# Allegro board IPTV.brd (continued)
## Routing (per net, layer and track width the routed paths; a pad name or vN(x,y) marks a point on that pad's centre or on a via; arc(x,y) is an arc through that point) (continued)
USBHUB4_FLG: length 59.3
  TOP w0.152: U8.2 v1(99.49,119.67) ; v1(102.85,108.06) 109.2,108.06 111.02,106.23 111.02,84.82 110.01,83.81 101.02,83.81 100.31,83.1 U1.39
  BOTTOM w0.152: v1(102.85,108.06) 102.85,118.4 102.08,119.16 99.8,119.16 99.49,119.47 v1(99.49,119.67) 99.49,120.25 R615.2
USBHUB4_PWREN: length 58.3
  TOP w0.152: v1(103.35,108.62) 103.61,108.37 109.32,108.37 111.33,106.36 111.33,84.7 110.13,83.5 101.35,83.5 100.81,82.97 U1.38 ; U8.1 v1(100.14,119.67)
  BOTTOM w0.152: R614.2 100.14,120.23 v1(100.14,119.67) 100.34,119.47 102.21,119.47 103.35,118.32 v1(103.35,108.62)
USBHUB4_VBUS: length 1.8
  TOP w0.406: C439.1 102.21,113.96
  BOTTOM w0.508: R650.1 v1(100.75,116.5)
VREG3P3: length 5.3
  TOP w0.203: R321.2 C365.1 129.64,40.42 129.26,40.8 129.26,41.11 127.97,42.41 U18.35
XIN\G: length 12
  TOP w0.152: IC13.A7 v2(83.55,25.56)
  BOTTOM w0.152: XL1.1 84.68,16.83 R186.1 83.8,25.56 v2(83.55,25.56) 83.55,25.32 83.16,24.93 C272.1
XOUT\G: length 3
  TOP w0.152: v2(83.55,26.36) 83.15,26.77 IC13.B7
  BOTTOM w0.152: v2(83.55,26.36) 83.72,26.2 R186.2 R187.2
XTAL_IN: length 8.3
  TOP w0.152: U18.39 132.31,44.01 C242.1 135.25,45.27 Y4.3
XTAL_OUT: length 8.2
  TOP w0.152: R351.1 132.33,43.61 U18.38
XTAL_VDD2P5: length 2.3
  TOP w0.203: U18.40 128.67,44.41 128.88,44.61 C367.1
N305458: length 11.8
  TOP w0.381: IC13.L17 v2(75.55,33.56)
  BOTTOM w0.381: v2(75.55,33.56) 75.47,33.65
  BOTTOM w0.508: L7.1 76.37,23.6 C25.2 76.37,26.2 75.67,26.9 75.67,33.45 v2(75.55,33.56) ; 75.47,33.65 C41.2
N331283: length 13.8
  TOP w0.381: v2(74.75,32.78) 74.76,32.78 IC13.K17
  BOTTOM w0.508: C20.2 74.4,21.68 L1.1 74.32,23.55 74.91,24.14 C40.2 74.91,32.63 v2(74.75,32.78)
N371060: length 3
  TOP w0.127: IC13.AN34 61.15,51.97 v2(61.15,53.57)
  BOTTOM w0.152: R36.1 61.21,53.63 v2(61.15,53.57)
N550713: length 12.4
  TOP w0.381: v2(77.15,33.56) 76.76,33.17 IC13.K15 ; v2(76.35,33.56) 75.96,33.17 IC13.K16 ; IC13.K14 77.56,33.17 v2(77.95,33.56)
  BOTTOM w0.381: C157.1 v2(77.95,33.56) ; C21.1 v2(76.35,33.56) ; v2(77.15,33.56) 77.15,32.85
  BOTTOM w0.508: C157.1 77.15,32.85 ; 77.15,32.85 77.09,32.78 C7.1 C173.1 79.25,30.71 79.27,30.73 L2.1 80.07,30.67 C19.1 ; 77.15,32.85 C21.1
N600656: length 19.6
  TOP w0.381: IC13.P17 75.15,35.56 v2(74.75,35.16) ; IC13.P15 76.75,36.37 76.35,36.76 v2(76.35,36.76) 75.96,36.37 IC13.P16
  BOTTOM w0.508: L3.1 72.94,21.77 C24.1 72.98,24.46 C162.1 C158.1 73,30.85 73.18,31.03 73.18,34.1 73.53,34.45 C175.1 73.95,34.71 74.41,35.16 v2(74.75,35.16) 75.15,35.16 75.64,35.65 C159.1 75.64,36.01 76.35,36.73 v2(76.35,36.76)
N617373: length 3.4
  TOP w0.152: R65.1 90.39,32.97 89.09,32.97 88.09,33.97 IC13.L1
N617477: length 4.4
  TOP w0.152: R66.1 90.39,33.27 89.22,33.27 88.12,34.37 87.56,34.37 IC13.L2
N620918: length 4.4
  TOP w0.152: v2(82.54,35.57) IC13.N10
  BOTTOM w0.152: v2(82.54,35.57) 82.54,34.69 83.1,34.14 R71.1
N621324: length 7.6
  TOP w0.356: IC13.T11 79.85,37.86 79.85,37.27 IC13.R11 79.95,37.17 v2(80.35,36.76)
  TOP w0.381: IC13.P11 79.96,36.37 v2(80.35,36.76)
  BOTTOM w0.381: L5.1 79.87,36.32 79.91,36.32 v2(80.35,36.76)
  BOTTOM w0.406: C196.2 80.75,37.16 v2(80.35,36.76)
  BOTTOM w0.457: C63.1 81.07,35.65 C196.2 C67.2
N624580: length 11.1
  TOP w0.381: 81.15,36.76 80.76,36.37 IC13.P10 ; 81.15,36.76 81.36,36.76 v2(81.64,36.49) ; 81.15,36.76 IC13.R10
  BOTTOM w0.381: C186.2 82.95,36.49 v2(81.64,36.49) ; C186.2 83.47,35.54 83.8,35.22 85.95,35.22 L6.1 86.08,34.58 86.08,32.87 C48.1 ; C186.2 C180.2
N629124: length 6.3
  TOP w0.127: 89.41,46.44 86.66,46.44 86.59,46.38 85.94,46.38 IC13.AG4
  TOP w0.152: R70.1 90.83,46.44 89.41,46.44
N629220: length 3.6
  TOP w0.152: IC13.AG3 89.63,46.77 R70.2
N630094: length 6.6
  TOP w0.381: IC13.W10 v2(84.69,40.37)
  BOTTOM w0.381: R67.1 86.23,39.75 85.62,40.37 v2(84.69,40.37)
N631154: length 11.7
  TOP w0.381: v2(80.35,40.77) IC13.Y11 79.06,41.17 78.75,40.86 v2(78.75,38.36) ; IC13.AA11 79.96,41.97 v2(80.35,42.37)
  BOTTOM w0.381: L8.1 79.12,38 v2(78.75,38.36) ; 81.07,41.57 C201.2 v2(80.35,40.77) ; 81.07,41.57 83.95,41.57 C199.1 ; 81.07,41.57 C200.2 80.5,42.22 v2(80.35,42.37)
N635359: length 14.1
  TOP w0.381: v2(84.35,44.77) 84.35,44.45 84.1,44.2 82.42,44.2 82.04,43.81 82.04,42.42 81.59,41.97 IC13.AA10 IC13.Y10
  BOTTOM w0.381: L16.1 88.81,45.21 87.29,46.74 C197.1 87,46.67 87,45.83 86.18,45.02 84.61,45.02 v2(84.35,44.77) 84.27,44.68 C198.2
N672491: length 5
  TOP w0.127: IC13.C2 88.37,27.57 88.46,27.47 88.88,27.47
  TOP w0.152: 88.88,27.47 R54.1 89.41,27.88 89.51,27.98 R56.2
N675190: length 6.8
  TOP w0.127: IC13.D2 87.54,28.76 88.11,28.76 88.36,29 88.36,29.76
  TOP w0.152: 88.36,29.76 88.36,30.38 88.88,30.9 R52.1 89.41,31.3 89.51,31.41 R53.2
N675584: length 6.2
  TOP w0.127: 88.11,27.98 86.74,27.98 IC13.D3
  TOP w0.152: 88.11,27.98 88.77,27.98 R49.1 89.41,29.02 89.51,29.12 R50.2
N683964: length 5.7
  TOP w0.127: IC13.AJ4 85.94,48.76 86.58,48.76 87.01,49.19 89.11,49.19
  TOP w0.152: R64.1 89.11,49.19
N742106: length 4.4
  TOP w0.152: v2(66.75,28.79) 68.33,28.79 68.75,28.37 IC13.D25
  BOTTOM w0.152: v2(66.75,28.79) 66.27,28.79 65.91,28.44 R193.1
N743329: length 1.4
  TOP w0.152: v2(76.35,27.16) 76.35,27.17 IC13.C16
  BOTTOM w0.152: R194.1 76.47,27.28 v2(76.35,27.16)
N743719: length 2.1
  TOP w0.152: IC13.K29 65.19,33.53 v2(65.02,33.53)
  BOTTOM w0.152: R195.1 v2(65.02,33.53)
N744113: length 1.9
  TOP w0.152: IC13.L28 66.35,33.96 v2(65.95,33.56)
  BOTTOM w0.152: 65.02,32.64 65.03,32.64 v2(65.95,33.56)
N849049: length 5.5
  TOP w0.152: v1(55.48,39.83) 55.47,39.83 55.72,39.58 59.94,39.58 IC13.V36
  BOTTOM w0.152: v1(55.48,39.83) 55.47,39.83 55.47,40.64 R189.1
N854645: length 1.4
  TOP w0.152: v2(60.35,31.16) 59.95,30.77 IC13.G36
  BOTTOM w0.152: R190.1 60.27,31.25 v2(60.35,31.16)
N855285: length 4.4
  TOP w0.152: IC13.AB29 64.75,42.77 v2(64.29,42.31)
  BOTTOM w0.152: R17.1 62.38,40.86 63.08,41.55 63.82,41.55 64.29,42.02 v2(64.29,42.31)
N858511: length 3.7
  TOP w0.127: IC13.AB28 66.35,42.76 65.95,42.37 65.33,42.37
  TOP w0.152: 65.33,42.37 65.24,42.37 v2(64.52,41.64)
  BOTTOM w0.152: R283.1 63.78,40.91 v2(64.52,41.64)
N952727: length 10.4
  TOP w0.381: v2(81.15,43.17) 80.76,42.77 IC13.AB10
  BOTTOM w0.381: v2(81.15,43.17) 81.55,43.57 C56.2 81.87,43.23 82.25,42.85 84.67,42.85 85.48,42.04 C26.2 87.25,42.04 L34.2
N952924: length 6.2
  TOP w0.381: v2(80.35,43.97) 79.96,43.57 IC13.AC11
  BOTTOM w0.381: C57.2 81.7,44.59 81.7,44.54 81.38,44.22 80.61,44.22 v2(80.35,43.97) 80.32,44 78.78,44 L35.2 78.75,43.98 78.75,42.37 C28.2
N965277: length 2.2
  TOP w0.127: IC13.AT27 v2(66.75,54.37)
  BOTTOM w0.381: R226.2 66.75,54.75 v2(66.75,54.37)
N968462: length 10.2
  TOP w0.381: IC13.AR27 v2(66.75,53.57) ; IC13.AT28 v2(65.95,54.37)
  BOTTOM w0.381: L36.2 69.83,58.27 C59.1 C58.1 66.72,58.27 66.39,57.94 66.39,56.55 C30.1 65.28,55.04 v2(65.95,54.37) v2(66.75,53.57)
N1067717: length 7.7
  TOP w0.381: v2(68.35,47.17) 68.75,47.57 IC13.AH25
  BOTTOM w0.381: C31.2 66.11,43.19 67.24,43.19 L37.1 68.33,44.28 68.33,45.19 68.17,45.34 68.17,45.35 67.99,45.53 67.98,45.53 67.62,45.9 ; C61.2 67.62,45.9 ; 67.62,45.9 67.86,45.9 68.33,46.37 68.33,47.14 v2(68.35,47.17)
N1077748: length 18.4
  TOP w0.127: 57.15,52.1 57.28,51.98 59.56,51.98 IC13.AP36
  TOP w0.152: 57.15,52.1 55.85,53.41 45,53.41 44.55,53.86 44.55,55.18 44.3,55.43 R232.1
N1078134: length 49.1
  TOP w0.152: R232.2 43.92,57.29 37.62,63.59 37.62,65.58 34.77,68.42 34.77,70.52 29.49,75.81 19.84,75.81 15.11,80.53 15.11,84.71 15.49,85.09 C243.2 R240.1
N1094266: length 4
  TOP w0.127: 57.56,54.71 57.92,54.36 59.31,54.36 59.7,53.97 IC13.AT36
  TOP w0.152: R241.1 56.87,55.4 57.56,54.71
N1103649: length 5.3
  TOP w0.152: IC13.AT33 61.96,54.36 61.96,55.77 59.92,57.81 R237.1
N1103990: length 3.9
  TOP w0.152: IC13.AU32 62.67,55.24 62.67,56.84 62.21,57.31 R238.1
N1109849: length 6
  TOP w0.127: IC13.AT34 61.16,54.36 60.58,54.36 60.34,54.59 60.34,54.93 59.83,55.44 59.83,55.97 59.46,56.35
  TOP w0.152: R239.1 58.42,57.39 59.46,56.35
N1115694: length 5.4
  TOP w0.127: v2(65.15,54.37) IC13.AT30
  BOTTOM w0.152: v2(65.15,54.37) 64.39,54.37 63.98,54.77 63.98,56.29 63.35,56.92 R294.1
N1152398: length 3.4
  TOP w0.152: R111.1 R485.2 60.45,72.07 JP1.3
N1152811: length 3.4
  TOP w0.152: JP1.2 60.45,74.61 R101.1 R479.2
N1383679: length 9.2
  TOP w0.127: IC13.AT12 79.15,55.46
  TOP w0.152: R75.2 79.48,61.53 79.48,59.85 79.38,59.75 R77.2 78.51,59.29 78.51,56.44 79.15,55.8 79.15,55.46
N1387604: length 7.3
  TOP w0.127: 80.36,55.88 80.36,54.33 80,53.97 IC13.AT11
  TOP w0.152: 80.36,55.88 80.36,57.18 C207.2 80.82,57.19 80.95,57.31 80.95,59.78 C202.2
N1390073: length 11.8
  TOP w0.381: v2(77.95,48.77) 77.55,48.37 IC13.AJ14 IC13.AH14 ; IC13.AJ13 78.35,48.37 v2(78.75,48.77) ; IC13.AR10 80.75,53.16 v2(80.35,52.77)
  BOTTOM w0.381: C214.1 79.16,49.17 v2(78.75,48.77) ; C214.1 79.28,49.85 L21.2 ; C214.1 79.16,49.97 80.32,51.13 C217.1 80.32,52.73 v2(80.35,52.77) ; v2(78.75,48.77) 79.47,48.05 C221.1 ; v2(78.75,48.77) v2(77.95,48.77) C220.1
N1408395: length 6.9
  TOP w0.127: 77.63,56.1 77.96,55.77 77.96,54.36 IC13.AT13
  TOP w0.152: 77.63,56.1 77.32,56.41 R76.2 77.6,57.09 77.9,57.39 77.9,59.17 R74.2
N1409767: length 2.8
  TOP w0.152: v2(77.95,53.57) 77.55,53.17 IC13.AR14
  BOTTOM w0.152: C212.2 C205.2 78.11,53.72 v2(77.95,53.57)
N1414099: length 11.6
  TOP w0.305: IC13.AJ15 76.75,48.37 v2(76.35,48.77) ; v2(75.55,47.97) IC13.AH16 IC13.AH15
  BOTTOM w0.381: v2(76.35,48.77) C219.1 75.64,48.05 v2(75.55,47.97) 74.84,48.68 C216.1 74.84,50.04 C213.1 75.13,51.31 75.59,51.78 C215.1 75.59,53.39 L22.2
N1446091: length 2.8
  TOP w0.127: IC13.AU20 72.75,54.77 v2(73.15,54.37)
  BOTTOM w0.152: R80.1 R79.1 73.15,55.37 v2(73.15,54.37)
N1450972: length 18.9
  TOP w0.381: IC13.AH20 v2(73.15,47.17) ; v2(70.75,53.57) 71.15,53.97 IC13.AT22 ; v2(70.75,52.77) 71.15,53.17 IC13.AR22 ; v2(73.15,48.77) 72.75,48.37 IC13.AJ20
  BOTTOM w0.381: C227.1 68.76,49.33 69.15,48.93 L24.1 ; C227.1 68.99,50.2 72.11,50.2 72.44,49.88 C236.1 72.75,49.44 73.15,49.03 v2(73.15,48.77) v2(73.15,47.17) 73.07,47.08 C233.1 ; C227.1 68.76,50.84 69.11,51.19 C231.1 69.11,53.04 C237.1 69.5,53.12 69.85,52.77 v2(70.75,52.77) v2(70.75,53.57) 70.77,53.54 C235.1
N1496909: length 3.3
  TOP w0.381: IC13.AT8 82.35,53.97 v2(82.75,53.57)
  BOTTOM w0.381: C234.1 83.55,55.4 C232.1 82.8,53.52 v2(82.75,53.57)
N1501073: length 3.5
  TOP w0.381: v2(81.95,54.37) 81.55,53.97 IC13.AT9
  BOTTOM w0.381: C223.1 v2(81.95,54.37) 80.53,54.37 C225.1
N1511391: length 11.9
  TOP w0.381: IC13.AJ10 80.75,48.37 v2(81.15,47.97) 80.76,47.57 IC13.AH10 ; IC13.AR8 82.35,53.14 81.95,52.74 81.95,52.27 82.26,51.97 v2(82.75,51.97)
  BOTTOM w0.381: v2(82.75,51.97) 82.84,51.88 C230.1 L23.1 84.39,50.27 84.62,50.04 C226.1 84.48,49.02 82.03,49.02 81.87,48.86 C229.1 81.87,48.27 81.57,47.97 v2(81.15,47.97)
N1721272: length 37.1
  TOP w0.406: v1(30.46,73.19) 30.71,73.19 31.39,72.5 31.39,64.1 31.34,64.05
  TOP w0.508: v1(13.16,64.07) C222.2 R9.2
  BOTTOM w0.406: v1(30.46,73.19) 18.14,73.19 14.2,69.25 14.2,65.1 v1(13.16,64.07)
N1729801: length 1.5
  TOP w0.508: T7.3 9.75,61.76 R9.1
N1743891: length 3
  TOP w0.406: 8.8,56.49 v1(8.74,56.43)
  TOP w0.508: T7.1 8.8,56.49
  BOTTOM w0.508: R69.1 v1(8.74,56.43)
N1825143: length 6.2
  TOP w0.508: C307.1 153.62,4.45 R509.2 151.15,4.22 C308.2 149.99,1.85 D37.3
N1834854: length 3.5
  TOP w0.152: LED10.1 103.63,10.3 103.63,12.2 R414.2
N1835472: length 4.4
  TOP w0.152: R355.1 R368.1 R365.1 R414.1
N1837681: length 11.6
  TOP w0.152: R410.1 v1(102.21,11.34) ; R365.2 105.37,11.86 T3.3 107.29,9.94 106.51,9.17 LED10.2
  BOTTOM w0.152: v1(102.21,11.34) 102.86,11.34 LED10.2
N1839934: length 1.3
  TOP w0.152: R410.2 102.19,13.74 T6.1
N1841130: length 2.6
  TOP w0.152: T6.3 99.92,9.2 LED10.3
N1846118: length 3
  TOP w0.152: R276.1 R273.2 108.18,13.93 T3.1
N1848580: length 1.4
  TOP w0.152: R271.2 R273.1
N1851731: length 7.5
  TOP w0.152: LED11.2 120.53,9.65 T4.3
  BOTTOM w0.152: LED11.2 121.2,10.32 R472.2 R473.1
N1851759: length 1.7
  BOTTOM w0.152: R473.2 126.3,9.05 T5.1
N1851767: length 15.4
  TOP w0.152: LED11.3 116.04,8.08 127.86,8.08 128.36,8.58 v1(128.36,9.05)
  BOTTOM w0.152: T5.3 v1(128.36,9.05)
N1851843: length 3
  TOP w0.152: R458.1 R457.2 125.92,8.7 T4.1
N1851925: length 2.8
  TOP w0.152: R474.2 117.45,9.21 LED11.1
N2007180: length 4.9
  TOP w0.381: C36.1 93.38,106.51 R163.1 94.08,103.99 R28.2
N2007522: length 2
  TOP w0.381: R28.1 92.52,101.85 IC9.6
N2007610: length 1.5
  TOP w0.152: TP31.1 91.25,101.34 IC9.7
N2007630: length 1.5
  TOP w0.152: IC9.8 89.98,101.34 TP30.1
N2053816: length 12.4
  TOP w0.381: R87.2 131.32,95.38 v1(131.19,95.25) 130.85,94.91 IC5.1
  TOP w0.406: C171.2 117.7,96.94
  BOTTOM w0.406: C92.1 131.89,95.95 v1(131.19,95.25) 130.21,94.27 v1(124.18,94.27)
N2054287: length 8
  TOP w0.381: IC5.2 v1(130.2,95.41) 130.43,95.63 130.43,97.54 130.81,97.92 R87.1 R85.2
  BOTTOM w0.381: C92.2 129.48,96.14 v1(130.2,95.41)
N2062131: length 3
  TOP w0.381: R100.2 126.96,95.42 IC5.7
N2068150: length 3.2
  TOP w0.381: IC5.4 128.91,95.63 127.95,96.58 C163.2
N2072854: length 1.3
  BOTTOM w0.406: C165.2 128.12,87.41 v1(128.25,87.29)
N2075428: length 2.3
  TOP w0.381: IC5.12 v1(129.55,87.37)
  BOTTOM w0.381: v1(129.55,87.37) 129.64,87.46 C165.1
N2101818: length 2.3
  TOP w0.381: C167.1 129.55,96.38 IC5.3
N2116419: length 2.5
  TOP w0.406: R255.1 103.9,97.03 ; R254.2 99.69,96.52 ; R301.2 102.11,96.52
N2117665: length 1.5
  TOP w0.381: T2.3 99.72,94.2 R254.1
N2151179: length 5
  TOP w0.381: T2.1 98.77,90.21 99.16,89.83 101.7,89.83 102.11,90.23 R103.1
N2292443: length 3
  BOTTOM w0.152: IC2.10 100.45,52.64 R143.1
N2293018: length 2.9
  BOTTOM w0.152: IC2.6 98.45,52.82 R142.1
N2300583: length 3.1
  BOTTOM w0.152: R144.1 R145.2 100.95,30.08 IC2.38
N2472672: length 2.9
  TOP w0.508: IC12.8 151.32,65.09 151.76,64.64 152.88,64.64 C86.1
N2473836: length 5.6
  TOP w0.508: IC12.6 v1(148.78,68.2)
  BOTTOM w0.508: C89.1 C174.1 v1(148.78,68.2)
N2474741: length 2.1
  BOTTOM w0.508: C89.2 R104.1
N2480908: length 5.3
  TOP w0.508: R123.1 R82.2 150.62,67.69 150.05,67.12 IC12.7
N2490139: length 2.6
  TOP w0.508: IC12.1 v1(151.32,69.92)
  BOTTOM w0.508: v1(151.32,69.92) 151.32,69.92 C93.2
N2491369: length 1.3
  BOTTOM w0.508: C93.1 v1(148.91,72.58)
N2496811: length 5.3
  TOP w0.508: IC12.5 147.51,67.13 147.21,67.44 R109.1 R108.2
N2616362: length 16.2
  TOP w0.406: C109.2 44.93,73.06
  TOP w0.508: v1(48.49,92.49) R60.2 47.16,92.49 46.84,92.18 46.84,88.37 C87.1 47.03,86.33 46.33,85.64 46.33,80.43
  BOTTOM w0.381: IC26.1 47.94,91.94 v1(48.49,92.49)
N2616386: length 4.1
  TOP w0.406: C97.2 40.36,89.19 v1(40.23,89.32)
  BOTTOM w0.406: v1(40.23,89.32) 40.26,89.34 IC26.10 ; IC26.11 40.27,89.99 v1(40.23,89.95)
  vias: v1(38.33,89.32) v1(38.33,88.68) v1(38.96,89.32) v1(38.96,88.68) v1(39.6,89.32) v1(39.6,88.68)
N2616524: length 4.4
  BOTTOM w0.381: IC26.7 48.62,88.04 R61.2 R134.1 R135.1
N2616548: length 2.4
  TOP w0.381: v1(40.36,90.64) 40.44,90.72 C97.1
  BOTTOM w0.381: IC26.12 v1(40.36,90.64)
N2616572: length 2.9
  BOTTOM w0.381: IC26.3 48.8,90.64 C108.1
N2616768: length 5.2
  TOP w0.381: 47.6,90.97 R60.1
  TOP w0.508: R60.1 48.17,90.97 v1(48.49,91.29) 48.62,91.16 R55.2 49.57,91.1 R15.2
  BOTTOM w0.381: IC26.2 v1(48.49,91.29)
N2616804: length 2.7
  BOTTOM w0.381: IC26.4 49.53,89.99 C94.2
N2642107: length 1.8
  BOTTOM w0.508: C115.1 13.82,56.26 IC14.8
N2642151: length 7.3
  BOTTOM w0.508: IC14.6 11.28,55.41 10.98,55.71 8.18,55.71 7.47,56.43 C117.1 C116.1
N2642251: length 2.3
  BOTTOM w0.508: C116.2 6.2,60.3 R116.1
N2642341: length 2.3
  BOTTOM w0.508: IC14.1 15.69,49.48 C120.2
N2642373:
  vias: v1(13.31,52.62) v1(13.31,51.85) v1(13.31,51.09) v1(14.07,52.62) v1(14.07,51.85) v1(14.07,51.09) v1(14.83,52.62) v1(14.83,51.85) v1(14.83,51.09)
N2642473: length 2.8
  BOTTOM w0.508: R124.1 IC14.7
N2642609: length 5.1
  BOTTOM w0.508: R121.1 7.98,51.27 R120.2 9.71,53.59 10.01,53.89 IC14.5
N2653412: length 1.5
  BOTTOM w0.508: IC17.8 31.28,3.82 C348.1
N2653456: length 3.4
  BOTTOM w0.508: IC17.6 33.15,7.75 C118.1 C349.1
N2653460: length 7.7
  TOP w0.508: v1(35.66,6.48) 34.04,6.48 33.53,5.97 31.64,5.97 R51.1
  BOTTOM w0.508: C347.2 v1(35.66,6.48) R125.2
N2653540: length 1.4
  BOTTOM w0.508: C349.2 R583.1
N2653646: length 2.5
  TOP w0.508: C350.2 24.8,5.27 v1(24.74,5.21)
  BOTTOM w0.508: IC17.1 v1(24.74,5.21)
N2653678: length 2.5
  TOP w0.508: C350.1 24.8,7.68 v1(24.74,7.75)
  BOTTOM w0.508: IC17.3 v1(24.74,7.75)
  vias: v1(22.07,8.55) v1(22.07,7.91) v1(22.71,8.55) v1(22.71,7.91) v1(23.34,8.55) v1(23.34,7.91) v1(23.98,8.55) v1(23.98,7.91)
N2653726: length 10
  TOP w0.406: C380.1 20.04,25.06 ; C354.1 18.77,25.06
  TOP w0.508: C351.1 28.37,16.47 30.42,14.43 R563.1
N2653778: length 3.3
  BOTTOM w0.508: IC17.7 R125.1 R89.2
N2653914: length 5.8
  TOP w0.508: v1(32.49,9.02) 31.9,9.6 R563.2 R567.1
  BOTTOM w0.508: v1(32.49,9.02) IC17.5
N2764036: length 0.6
  TOP w0.406: C119.2 157.71,90.81 157.82,90.82
N2794854: length 3.3
  TOP w0.508: LED1.2 139.97,91.69 R122.1
N2987765: length 10
  BOTTOM w0.152: XL1.2 86.74,18.33 86.74,22.9 86.49,23.15 C274.1 R187.1
N4126175: length 3.4
  TOP w0.152: U1.47 96.31,84.38 R584.1 96.28,84.42 R585.2
N4126191: length 11.9
  TOP w0.254: U1.18 98.31,72.41 v1(98.31,72.4) ; U1.16 v1(97.31,72.43)
  TOP w0.508: R587.1 v1(96.75,68.83) 97.87,68.83 L49.2
  BOTTOM w0.381: v1(96.75,68.83) 96.75,71.98 97.19,72.43 v1(97.31,72.43) 97.04,72.7 C414.1 97.8,73.21 97.95,73.37 C413.1 98.31,72.4 v1(98.31,72.4)
N4126235: length 3.5
  TOP w0.203: U1.29 103.75,77.16 103.81,77.1 104.27,77.1 arc(104.57,77.04) 104.83,76.87 arc(105.08,76.7) 105.38,76.64 105.57,76.64 arc(105.84,76.75) R595.1
N4126359: length 3.5
  TOP w0.203: U1.28 103.75,76.66 103.78,76.69 104.27,76.69 arc(104.42,76.66) 104.54,76.58 arc(104.92,76.33) 105.38,76.24 105.6,76.24 arc(105.85,76.13) R594.1
N4126443: length 4.6
  TOP w0.152: U1.13 95.81,72.63 95.64,72.45 93.61,72.45 R586.2
N4126465: length 3.8
  TOP w0.203: U1.26 103.65,75.66 arc(103.69,75.65) 103.73,75.63 103.91,75.63 arc(104.08,75.59) 104.22,75.5 105.18,74.54 arc(105.37,74.41) 105.59,74.37 arc(105.85,74.48) R593.1
N4126501: length 3.9
  TOP w0.203: U1.25 103.7,75.16 103.76,75.22 103.91,75.22 arc(103.92,75.22) 103.93,75.21 104.89,74.25 arc(105.21,74.04) 105.59,73.96 arc(105.85,73.86) R592.1
N4126581: length 14.2
  TOP w0.508: R585.1 95.35,86.52 C405.1 95.13,86.52 C404.1 89,86.52 84.94,90.59 L47.2
N4126617: length 2.9
  TOP w0.152: R590.1 92.11,74.38 93.39,75.66 U1.11
N4126645: length 2.9
  TOP w0.254: R587.2 95.64,71.45 96.81,72.62 U1.15
N4126967: length 12.1
  TOP w0.254: U1.17 v1(97.81,75.11) ; U1.19 v1(98.81,75.11)
  TOP w0.381: L48.2 v1(102.37,72.58)
  BOTTOM w0.381: C414.2 97.41,75.11 v1(97.81,75.11) v1(98.81,75.11) 98.31,74.61 98.31,74.34 C413.2 98.72,74.33 98.94,74.1 98.94,73.64 99.24,73.34 101.61,73.34 v1(102.37,72.58)
N4126991: length 4.2
  TOP w0.152: R588.2 93.99,71.84 94.3,72.15 95.76,72.15 96.31,72.7 U1.14
N4127321: length 3.8
  TOP w0.203: U1.34 103.62,79.66 103.65,79.7 103.95,79.7 arc(104.22,79.75) 104.46,79.91 105.3,80.75 arc(105.38,80.8) 105.48,80.82 105.59,80.82 arc(105.85,80.71) R598.1
N4127377: length 3.8
  TOP w0.203: R599.1 105.96,81.57 arc(105.85,81.32) 105.59,81.23 arc(105.53,81.23) 105.48,81.23 arc(105.22,81.18) 105.01,81.03 104.17,80.19 arc(104.07,80.13) 103.95,80.1 103.68,80.1 103.62,80.16 U1.35
N4127493: length 3.5
  TOP w0.203: U1.32 103.59,78.66 103.64,78.61 104.26,78.61 arc(104.32,78.62) 104.37,78.66 arc(104.69,78.87) 105.06,78.94 105.59,78.94 arc(105.85,79.05) R597.1
N4127601: length 3.5
  TOP w0.203: U1.31 103.6,78.16 103.64,78.21 104.26,78.21 arc(104.48,78.25) 104.66,78.37 arc(104.84,78.49) 105.06,78.54 105.59,78.54 arc(105.85,78.43) R596.1
N4207901: length 3.4
  TOP w0.152: R600.1 91.83,78.67 93.35,77.16 U1.8
N4556901: length 2.8
  TOP w0.152: U5.5 127.93,103.42 127.51,103 R607.1
N4601170: length 2.2
  TOP w0.356: U6.5 154.78,45.25 R610.1
N4602996: length 2
  BOTTOM w0.152: U7.5 145.9,33.19 R613.1
N4604860: length 2.5
  TOP w0.152: R616.1 98.02,117.89 98.19,117.73 U8.5
N4652480: length 7.3
  TOP w0.152: R617.2 C0603.1 45.24,48.64 40.73,48.64 40.49,48.4 40.49,47.77 U9.T2
N4662264: length 5.4
  TOP w0.102: U9.L8 34.9,42.98 v1(33.42,42.98)
  BOTTOM w0.152: v1(33.42,42.98) 33.42,42.73 31.62,40.93 R618.2
N4946648: length 4.4
  TOP w0.102: U10.L8 46.1,9 46.1,7.43 46.04,7.37
  TOP w0.152: 46.04,7.37 46.04,7.24 v1(45.31,6.51)
  BOTTOM w0.152: v1(45.31,6.51) 45.06,6.26 R635.2
N4946958: length 7.9
  TOP w0.152: U10.T2 42,14.73 v1(42,18.33)
  BOTTOM w0.152: v1(42,18.33) 40.86,19.47 C473.1 39,19.47 R638.2
N5731377: length 2.4
  TOP w0.152: U11.5 v1(93.73,57.21)
  BOTTOM w0.152: v1(93.73,57.21) 93.42,56.91 R157.1
N5731391: length 2.3
  TOP w0.152: U11.2 v1(91.19,50.08)
  BOTTOM w0.152: R112.2 91.16,50.05 v1(91.19,50.08)
N5767868: length 5.1
  TOP w0.152: IC13.AT32 62.26,54.86 62.26,56.24 61.06,57.44 R160.1
N5876384: length 7.7
  TOP w0.127: IC13.AR30 64.36,53.56 64.36,55.71 64.01,56.07 64.01,56.77
  TOP w0.152: 64.01,56.77 64.01,59.85 R292.1
N5917875: length 2.8
  TOP w0.152: IC13.AV32 63.12,55.6 63.12,56.93 63.35,57.16 R296.1
N6200242: length 10.6
  TOP w0.305: R315.1 R316.1 R298.1 ; IC8.32 26.45,84.55 27.37,85.47 29.34,85.47 30.1,86.23 C239.1 R298.1 ; R298.1 31.73,86.13 R367.1
N6200318: length 5.7
  TOP w0.152: C113.2 19.3,83.06 19.43,83.19 R113.1 19.79,84.05 IC8.10
N6200334: length 1.4
  TOP w0.152: R114.2 32.41,83.27 LED5.2
N6200500: length 1.9
  TOP w0.152: R118.1 27.31,82.55 IC8.28
N6200912: length 3.3
  TOP w0.152: IC8.26 26.52,81.55 27.08,81 27.08,79.79 27.33,79.54 R299.2
N6200944: length 2.3
  TOP w0.152: R300.2 26.54,82.05 IC8.27
N6201102: length 40.2
  TOP w0.152: IC8.18 22.37,78.21 23.76,76.82 29.77,76.82 35.69,70.9 35.69,68.8 38.53,65.95 38.53,63.97 43.34,59.17 46.76,59.17 47.75,58.18 R302.2
N6210871: length 6.2
  TOP w0.508: R307.1 9.37,114.78 XS11.A8 9.34,116.09 XS11.A7
N6210911: length 2.5
  BOTTOM w0.152: C152.2 R303.2 R309.2
N6210999: length 15.8
  BOTTOM w0.152: TR2.16 16.84,106.88 16.84,111.51 15.54,112.81 15.54,115.28 16.77,116.52 17.39,116.52 XS11.A1
N6211019: length 16.1
  BOTTOM w0.152: TR2.14 17.14,106.93 17.14,111.63 15.84,112.94 15.84,115.16 16.9,116.21 17.47,116.21 17.73,115.95 17.73,115.58 XS11.A2
N6211031: length 6.2
  TOP w0.508: R306.1 14.42,111.77 XS11.A4 14.42,116.09 XS11.A5
N6211051: length 28.2
  BOTTOM w0.152: XS11.A3 15.69,116.27 15.49,116.08 14.86,116.08 14.57,116.36 14.57,118.15 14.99,118.57 18.92,118.57 29.57,107.93 29.57,106.91 TR2.11
N6211151: length 2.3
  TOP w0.508: R305.1 TR2.15
N6211171: length 2.3
  TOP w0.508: R304.1 TR2.10
N6211183: length 29.7
  BOTTOM w0.152: XS11.A6 12.58,114.82 14.27,116.5 14.27,118.28 14.86,118.87 19.05,118.87 29.87,108.05 29.87,106.91 TR2.9
N6211413: length 2.5
  BOTTOM w0.152: C151.2 R308.1 R310.1
N6211447: length 29
  TOP w0.508: C161.2 30.16,109.28 R304.2 R305.2 14.49,109.28 R306.2 14.42,109.28 9.41,109.28 R307.2
N6323561: length 42.5
  TOP w0.152: R154.2 45.21,57.88 44.53,58.56 43.08,58.56 37.92,63.72 37.92,65.7 35.08,68.55 35.08,70.65 29.62,76.11 20.57,76.11 20.17,76.52 20.17,81 20.72,81.55 IC8.15
N6351542: length 1.9
  TOP w0.152: IC8.13 20.65,82.55 20.4,82.3 R314.2
N6375056: length 3.9
  TOP w0.152: R126.1 24.47,88.25 24.47,87.41 23.77,86.72 23.77,85.87 23.87,85.77 IC8.4
N6376252: length 3.9
  TOP w0.152: R127.1 24.17,88.25 24.17,87.54 23.47,86.84 23.47,85.87 23.37,85.77 IC8.5
N6391887: length 4
  TOP w0.152: IC8.6 22.87,85.77 22.77,85.87 22.77,86.95 22.12,87.6 22.12,88.19 R128.1
N6393086: length 4
  TOP w0.152: R129.1 21.82,88.19 21.82,87.48 22.47,86.83 22.47,85.87 22.37,85.77 IC8.7
N6403944: length 1.8
  TOP w0.152: IC8.30 27.58,83.55 R130.1
N6828557: length 2
  TOP w0.152: R131.1 27.22,84.05 IC8.31
N6828959: length 1.3
  TOP w0.152: R131.2 TP33.1
N7088770: length 3.9
  BOTTOM w0.406: v1(53.7,73.06) C27.1 v1(52.62,74.14) ; v1(51.96,74.17) 51.96,74.34 52.3,74.68 C29.1 ; R19.2 v1(54.33,74.33)
N7088794: length 5
  TOP w0.508: U13.1 v1(55.87,78.52)
  BOTTOM w0.508: R19.1 R12.2 C46.2 55.86,78.51 v1(55.87,78.52)
N16840469: length 11.3
  TOP w0.127: IC13.R3 86.68,37.17 86.78,37.07 88.78,37.07 89,37.29 89.41,37.29
  TOP w0.152: R323.1 94.45,37.29 89.41,37.29
N16871257: length 12
  TOP w0.127: 89.41,37.59 88.89,37.59 88.62,37.32 86.88,37.32 86.65,37.56 86.15,37.56 85.74,37.97 IC13.T4
  TOP w0.152: 89.41,37.59 94.58,37.59 95.94,36.23 R325.1
N16883109: length 2.4
  TOP w0.152: IC13.B4 85.98,26.34 R327.1
N16907829: length 10.8
  TOP w0.127: IC13.T3 86.6,37.97 86.99,37.58 88.44,37.58 88.76,37.9 89.41,37.9
  TOP w0.152: 89.41,37.9 94.7,37.9 95.22,37.38 R328.1
N16928233: length 3.1
  TOP w0.127: IC13.N1 88.06,35.68 89.38,35.68 89.41,35.65
  TOP w0.152: 89.41,35.65 90.37,35.65 C358.2
N16929752: length 4
  TOP w0.127: IC13.N2 87.4,35.57 87.79,35.96 89.41,35.96
  TOP w0.152: 89.41,35.96 90.4,35.96 C359.2
N17005896: length 2.5
  BOTTOM w0.152: R107.1 107.75,93.26 T8.1
N17005931: length 6.9
  BOTTOM w0.508: C88.1 109.51,88.87 R331.1 107.93,88.68 Q10.1 R330.2 R322.2
N17006006: length 1.4
  BOTTOM w0.508: T8.3 R330.1
N17042686: length 2.7
  TOP w0.203: U18.44 128.31,46.01 129.33,47.03 C250.1
N17042698: length 6.1
  TOP w0.152: U18.46 128.21,46.81 129.68,48.27 132.06,48.27 R353.2
N17042736: length 3.5
  TOP w0.254: C372.1 117.98,22.52 C323.1 117.93,22.52 ANT1.1
N17042751: length 2.5
  TOP w0.254: R252.1 120.47,34.84 120.47,34.84 L44.2 120.47,33.54 C373.2
N17042774: length 4.9
  TOP w0.254: R334.1 126.47,34.71 ; 126.47,34.71 C240.1 126.47,34.71 ; 126.47,34.71 L39.2 L42.2 C332.2
N17042778: length 1.2
  TOP w0.254: L40.2 128.6,34.71 C240.2
N17042826: length 1.7
  TOP w0.152: U18.1 118.85,48.81 118.31,49.34 R335.2
N17042890: length 4.4
  TOP w0.254: ANT2.1 137.79,23.94 C376.1 137.77,27.11 C324.1
N17042953: length 3
  TOP w0.152: Y4.1 136.97,41.25 C224.1 R351.2
N17043028: length 4.2
  TOP w0.152: R340.1 128.5,39.92 128.25,40.17 128.25,41.61 127.8,42.06 126.94,42.06 126.84,41.95 U18.34
N17043046: length 1.5
  TOP w0.203: 120.44,41 U18.18
  TOP w0.254: C327.2 120.44,40.27 120.44,41
N17043052: length 8.2
  TOP w0.203: 122.04,40.27 U18.22
  TOP w0.254: 122.04,40.27 122.04,33.55 C334.2
N17043079: length 1.5
  TOP w0.152: C356.2 121.92,53.38 121.92,53.76 R337.1
N17043089: length 1.6
  TOP w0.152: R339.1 122.23,53.73 122.23,53.4 C357.2
N17043097: length 2.9
  TOP w0.152: C357.1 122.24,51.59 122.24,51.47 122.8,50.92 122.8,50.25 122.84,50.22 U18.62
N17043198: length 4.4
  TOP w0.152: U18.55 125.64,49.95 125.96,50.27 127.3,50.27 128.37,51.35 R319.1
N17043200: length 2.9
  BOTTOM w0.381: U23.4 112.01,42.43 111.74,42.71 L43.1
N17043207: length 7.6
  TOP w0.152: U18.47 128.18,47.21 129.55,48.58 131.45,48.58 132.72,49.85 R342.2 R338.1
N17043263: length 4.2
  BOTTOM w0.381: U23.6 113.31,43.68 R350.2 R348.2 C335.2
N17043371: length 1.7
  TOP w0.203: 126.04,40.8 U18.32
  TOP w0.254: C228.2 126.04,40.58 126.04,40.8
N17043377: length 13.6
  TOP w0.203: 124.44,40.36 U18.28
  TOP w0.254: C238.2 125.07,29.76 124.44,30.39 124.44,40.36
N17043650: length 1.5
  TOP w0.152: R29.1 LED8.1
N17043923: length 2.9
  TOP w0.152: U18.60 123.64,50.18 123.67,50.22 123.67,50.8 124.22,51.35 124.22,51.58 C194.1
N17044492: length 5.5
  TOP w0.152: U18.65 121.64,49.92 121.59,49.97 121.59,50.37 119.95,52.01 119.95,53.75 R343.1
N17044502: length 5.5
  TOP w0.152: R347.1 119.65,53.74 119.65,51.88 121.28,50.24 121.28,49.97 121.24,49.92 U18.66
N17044512: length 2.9
  TOP w0.152: U18.63 122.44,50.2 122.49,50.25 122.49,50.79 121.93,51.35 121.93,51.58 C356.1
N17044516: length 2.9
  TOP w0.152: C193.1 124.53,51.59 124.53,51.22 123.98,50.67 123.98,50.23 124.04,50.18 U18.59
N17044572: length 3.3
  TOP w0.152: U18.58 124.44,50.6 125.31,51.47 125.55,51.47 R341.1
N17044582: length 4
  TOP w0.152: R332.1 126.39,51.17 125.52,51.17 124.84,50.49 U18.57
N17044593: length 47.4
  TOP w0.152: U18.48 128.15,47.61 129.42,48.88 131.24,48.88 131.67,49.31 131.67,52.64 v1(131.06,53.25) ; v1(104.45,37.6) 104.34,37.5 R324.1
  BOTTOM w0.152: v1(131.06,53.25) 112.5,53.25 104.7,45.45 104.7,37.85 v1(104.45,37.6)
N17408441: length 4.3
  TOP w0.254: C387.1 149.1,14.77 C385.1 149.07,13.6 149.07,10.7 ANT3.1
N17408443: length 9.9
  TOP w0.254: ANT6.1 140.49,16.93 C386.1 149.1,15.79 C387.2
N17411597: length 3.6
  TOP w0.254: ANT4.1 10.01,87.77 C388.1 10.14,87.9 C390.1
N17411599: length 6.4
  TOP w0.254: ANT5.1 10.16,91.1 C389.1 10.16,89.95 C390.2
N17473278: length 2.3
  TOP w0.152: IC9.1 89.98,92.68 R115.2
N17474165: length 2.3
  TOP w0.152: IC9.2 91.25,92.68 R117.2
N17571775: length 16.3
  TOP w0.508: D5.2 v1(92.81,24.87)
  BOTTOM w0.508: L2.2 81.62,30.64 83.41,30.64 85.4,28.66 88.06,28.66 90.46,26.26 90.46,25.12 R178.2 90.72,24.87 v1(92.81,24.87)
N17602669: length 3.3
  TOP w0.152: R256.2 U20.2 R20.1
N17602677: length 6.8
  TOP w0.152: C391.1 R397.2 R357.2 R356.2 73.51,11.09 U20.3
N17621483: length 3.3
  TOP w0.254: R136.1 C60.2 65.58,102.37 U22.13
N17621510: length 4.8
  TOP w0.254: R7.2 63.53,104.3 63.27,104.56 63.27,106.56 63.55,106.84 R247.1 R258.2
N17621572: length 9.4
  TOP w0.254: R137.2 70.97,99.33 C181.1 70.99,99.88 71.22,100.11 76.3,100.11 76.56,100.37 R317.1 R359.1
N17621582: length 2.6
  TOP w0.254: U22.8 v1(68.3,105.62)
  BOTTOM w0.254: C34.2 68.35,105.57 v1(68.3,105.62)
N17621588: length 2.6
  TOP w0.254: U22.11 66.32,103.67 65.68,104.3 R7.1
N17621590: length 1.5
  TOP w0.254: U22.6 74.77,104.97 C35.2
N17621599: length 11.3
  TOP w0.254: R257.2 70.52,107.69 70.52,107.19 R360.1 70.52,106.5 70.52,103.29 70.79,103.02 U22.3 74.92,103.02 C62.2 R359.2
N17621615: length 3.1
  TOP w0.254: R317.2 C62.1 74.83,102.37 U22.2
N17621623: length 2.8
  TOP w0.254: R137.1 70.64,96.76 70.64,95.49 70.9,95.22 C268.2
N17621625: length 2.5
  TOP w0.254: U22.7 v1(72.24,105.62)
  BOTTOM w0.254: C34.1 72.19,105.57 v1(72.24,105.62)
N17621631: length 11.3
  TOP w0.254: R358.1 C60.1 65.5,103.02 U22.12 69.75,103.02 70.02,103.29 70.02,106.5 R133.1 70.02,107.19 70.02,107.69 R361.1
N17621647: length 9.6
  TOP w0.254: R90.1 69.8,98.08 C182.1 69.8,99.63 69.44,99.99 64.36,99.99 63.86,100.49 R136.2 63.98,101 R358.2
N17621657: length 2.8
  TOP w0.254: C393.1 69.94,95.22 70.13,95.41 70.13,96.79 R90.2
N17621659: length 6.7
  TOP w0.254: U22.5 75.28,104.32 R246.1 77.79,104.96 C53.1 R88.2
N17668644: length 5.4
  BOTTOM w0.508: Q9.1 19.41,34.96 R165.1 R10.2 19.41,29.9 C255.2
N17668703: length 2
  BOTTOM w0.508: T9.3 16.09,32.17 R10.1
N17668713: length 1.7
  BOTTOM w0.152: T9.1 13.96,29.64 R164.1
N17692840: length 6.7
  TOP w0.127: IC13.AU36 59.54,55.18 59.54,55.84 59.31,56.07
  TOP w0.152: R363.1 57.76,57.62 59.31,56.07
N17694055: length 6.5
  TOP w0.127: IC13.AU35 60.75,55.01 60.3,55.47 60.3,55.94 59.47,56.77
  TOP w0.152: R364.1 59.04,60.5 59.04,57.2 59.47,56.77
N17732186: length 3.1
  TOP w0.152: R171.2 81.76,55.16 81.37,54.77 IC13.AU10
N17732471: length 4.5
  TOP w0.152: R172.2 81.26,59.12 81.26,56.07 IC13.AV10
N17732758: length 2
  TOP w0.127: IC13.AV11 79.95,56.36 79.54,56.77
  TOP w0.152: 79.54,56.77 R173.2
N17739492: length 4.8
  TOP w0.152: IC13.AV14 76.73,56.39 76.73,59.19 R177.1
N17739788: length 2.9
  TOP w0.152: IC13.AU14 76.38,55.94 76.38,56.88 R176.1
N17782138:
  vias: v1(51.79,64.3) v1(51.79,63.41) v1(51.79,62.52) v1(52.55,64.3) v1(52.55,63.41) v1(52.55,62.52)
N17812204: length 3.1
  TOP w0.152: R475.2 133.83,6.53 LED12.1
N17850380: length 1.7
  TOP w0.152: R397.1 TP19.1

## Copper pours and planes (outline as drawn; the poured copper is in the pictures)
1V0\G on TOP: 46.71,67.73 46.71,62.27 46.46,62.01 44.17,62.01 43.92,62.27 43.92,67.73 44.3,68.11 46.33,68.11
1V0\G on BOTTOM: 44.3,65.44 44.04,65.7 44.04,67.73 44.43,68.11 49,68.11 49.12,67.98 49.12,65.57 49,65.44
1V0_CTRL\G on TOP: 47.47,73.44 49.76,73.44 50.01,73.19 50.01,70.14 49.76,69.89 47.6,69.89 47.35,70.14 47.35,73.32
1V0_CTRL\G on BOTTOM: 47.22,72.05 49.76,72.05 50.01,71.79 50.01,69.38 49.76,69.13 47.22,69.13 46.97,69.38 46.97,71.79
1V0_CTRL\G on L03_P2: 60.12,34.91 60.12,41.14 58.98,42.29 58.98,46.31 59.24,46.57 60.64,46.57 61.01,46.94 61.01,48.13 60.64,48.5 58.86,48.5 51.62,55.74 47.55,55.74 47.55,71.84 47.81,72.1 52.98,72.1 53.62,71.45 53.62,61.17 55.9,58.89 70,58.89 71.78,57.1 71.78,47.45 72.66,46.57 78.89,46.57 79.4,46.05 79.4,35.94 78.38,34.91
1V5_DDR3\G on TOP, BOTTOM: 30.58,26.96 35.66,26.96 35.92,26.71 35.92,24.8 35.66,24.55 30.58,24.55 30.33,24.8 30.33,26.71
1V5_DDR3\G on L03_P2: 41.97,6.08 40.31,7.74 40.31,13.2 34.72,18.79 34.72,30.22 29.77,35.17 29.77,50.37 34.73,55.33 51.45,55.33 58.69,48.09 60.47,48.09 60.6,47.96 60.6,47.11 60.47,46.98 59.07,46.98 58.57,46.48 58.57,42.12 59.72,40.97 59.72,34.03 58.57,32.89 58.57,26.88 59.07,26.38 64.96,26.38 65.46,26.88 65.46,28.66 65.85,29.04 67.46,29.04 67.84,28.66 67.84,22.94 71.65,19.14 76.85,19.14 77.24,18.75 77.24,18.28 76.98,18.02 75.52,18.02 73.43,15.93 73.43,8.88 72.79,8.24 57.42,8.24 56.79,7.61 56.79,6.22 56.66,6.08
1V5_DDR3_PHY\G on TOP: 64.52,27.43 64.14,27.81 64.14,28.57 63.88,28.83 63.37,28.83 61.47,30.73 61.47,31.37 61.72,31.62 61.72,34.04 61.59,34.16 59.82,34.16 59.69,34.29 59.69,34.8 59.82,34.92 61.47,34.92 61.59,35.05 61.59,38.99 61.34,39.24 60.58,39.24 60.45,39.37 60.45,39.66 60.64,39.85 60.66,39.85 61.34,40.54 61.34,41.02 61.21,41.15 61.09,41.15 60.83,40.89 60.58,40.89 60.45,41.02 60.45,41.27 61.34,42.16 61.34,46.74 60.96,46.74 60.45,46.23 60.2,46.23 59.82,46.61 59.82,46.99 60.71,46.99 61.34,47.62 61.34,49.78 59.69,51.44 59.69,51.56 59.82,51.69 60.07,51.69 60.58,51.18 64.39,51.18 64.64,50.93 64.64,42.16 65.02,41.78 66.04,41.78 66.17,41.66 66.17,41.02 67.94,41.02 68.2,40.77 68.2,36.58 69.41,35.37 72.07,35.37 75.44,32 75.44,29.72 75.06,29.34 65.28,29.34 65.02,29.08 65.02,27.56 64.9,27.43
1V5_DDR3_PHY\G on BOTTOM: 27.53,25.06 27.53,27.85 27.79,28.1 29.31,28.1 29.57,27.85 29.57,25.06 29.31,24.8 27.79,24.8
1V5_DDR3_PHY\G on L03_P2: 37.94,2.24 27.36,12.82 27.36,28.02 28,28.66 34.32,28.66 34.32,18.62 39.9,13.03 39.9,7.57 41.8,5.68 56.83,5.68 57.2,6.05 57.2,7.45 57.59,7.83 72.96,7.83 73.84,8.72 73.84,15.77 75.69,17.61 77.15,17.61 77.65,18.11 77.65,18.92 77.02,19.54 71.81,19.54 68.25,23.11 68.25,28.82 67.62,29.45 65.68,29.45 65.05,28.82 65.05,27.05 64.79,26.78 59.24,26.78 58.98,27.05 58.98,32.72 60.12,33.86 60.12,34.5 76.53,34.5 76.53,27.08 80.54,23.07 80.54,5.96 76.82,2.24
2V5\G on TOP: 135.89,71.79 136.27,72.17 136.27,78.11 135.76,78.61 125.09,78.61 124.21,77.72 124.21,72.26 124.68,71.79
3V3\G on TOP: 50.39,79.54 52.3,79.54 52.55,79.29 52.55,76.49 52.3,76.24 50.39,76.24 50.14,76.49 50.14,79.29
3V3\G on TOP: 14.33,74.33 14.83,74.84 22.26,74.84 23.72,73.38 26.71,73.38 27.28,72.81 27.28,65.7 26.9,65.32 15.09,65.32 14.33,66.08
3V3\G on TOP: 33.38,60.24 33.12,60.49 33.12,63.41 33.25,63.54 36.04,63.54 36.3,63.28 36.3,60.49 36.04,60.24
3V3\G on BOTTOM: 52.3,82.59 52.55,82.33 52.55,78.14 52.3,77.89 50.27,77.89 50.14,78.02 50.14,82.33 50.39,82.59
3V3\G on L03_P2: 34.85,55.74 34.85,57.14 33.59,58.41 27.49,58.41 23.04,62.86 23.04,71.45 23.43,71.84 26.31,71.84 26.7,71.45 26.7,66.25 29.61,63.33 36.64,63.33 37.9,64.6 37.9,73.49 44,79.59 52.72,79.59 52.86,79.46 52.86,72.5 47.64,72.5 47.14,72 47.14,55.74
3V3_MOS\G on TOP: 79.48,38.39 79.73,38.14 81.64,38.14 82.91,36.87 82.91,34.84 82.65,34.58 80.49,34.58 80.11,34.96 78.59,34.96 78.08,34.45 78.08,30.9 77.19,30.01 77.19,28.1 77.32,27.98 78.46,27.98 79.22,28.74 80.11,28.74 80.24,28.61 80.24,28.23 80.11,28.1 80.11,27.72 80.37,27.47 81.13,27.47 81.38,27.72 81.38,28.61 81.51,28.74 82.53,28.74 83.29,29.5 84.3,29.5 84.43,29.37 84.43,28.87 84.68,28.61 86.72,28.61 86.84,28.74 86.84,31.66 85.19,33.31 85.19,38.01 85.32,38.14 86.34,38.14 86.46,38.26 86.46,38.9 86.34,39.03 84.68,39.03 83.8,39.92 81.38,39.92 80.75,39.28 79.73,39.28 79.48,39.03
3V3_MOS\G on TOP: 35.92,64.05 35.79,63.92 32.49,63.92 31.85,64.55 31.85,66.2 32.11,66.46 35.54,66.46 35.92,66.08
3V3_MOS\G on TOP: 65,50.96 65,43.34 65.25,43.09 68.17,43.09 68.43,43.34 68.43,45.76 68.68,46.01 78.21,46.01 78.59,45.63 78.59,44.36 78.84,44.11 83.54,44.11 84.68,42.96 86.21,42.96 86.59,43.34 86.59,43.73 86.46,43.85 85.32,43.85 85.19,43.98 85.19,50.46 86.34,51.6 86.34,52.23 85.83,52.74 83.41,52.74 83.16,52.49 83.16,51.85 83.03,51.73 82.02,51.73 81.26,52.49 74.4,52.49 74.02,52.87 74.02,53.38 73.89,53.5 73.25,53.5 72.75,53 72.75,52.49 72.49,52.23 68.3,52.23 68.05,52.49 68.05,52.87 68.17,53 68.17,53.38 68.05,53.5 67.41,53.5 66.4,52.49 64.75,52.49 64.24,53 64.24,55.79 63.73,56.3 63.48,56.3 63.22,56.04 63.22,53.12 62.84,52.74 61.57,52.74 61.44,52.62 61.44,51.98 61.95,51.47 64.49,51.47
3V3_MOS\G on BOTTOM: 111.86,35.98 112.12,36.23 114.4,36.23 114.66,35.98 114.66,33.18 114.4,32.93 112.24,32.93 111.86,33.31
3V3_MOS\G on BOTTOM: 24.38,79.5 24.38,76.33 24,75.95 21.46,75.95 21.21,76.2 21.21,79.5 21.46,79.76 24.13,79.76
3V3_MOS\G on L03_P2: 80.95,12.43 80.95,23.24 76.94,27.25 76.94,34.5 78.55,34.5 79.81,35.77 79.81,46.22 79.05,46.98 72.83,46.98 72.19,47.62 72.19,57.27 70.16,59.3 56.07,59.3 54.03,61.34 54.03,71.62 53.26,72.38 53.26,82.63 54.25,83.62 116.76,83.62 116.93,83.46 121.18,79.21 138.58,79.21 144.96,72.82 152.23,72.82 152.86,73.45 152.86,75.01 149.28,78.59 149.28,87.5 145.98,90.79 134.13,90.79 132.35,89.01 125.41,89.01 123.16,91.26 84.04,91.26 80.96,94.35 40.15,94.35 34.95,89.15 34.95,83.69 28.97,77.71 16.94,77.71 16.21,78.44 16.21,89.87 15.71,90.37 14.56,90.37 14.05,90.89 14.05,100.04 39.68,100.04 40.69,101.05 40.69,106.29 34.73,112.25 29.4,112.25 23.71,117.94 38.29,117.94 39.81,119.47 49.55,119.47 53.23,115.78 91.63,115.78 97.6,121.75 102.63,121.75 103.66,120.73 103.66,108.54 104.41,107.78 142.51,107.78 151.02,99.27 161.69,99.27 166.52,94.44 166.52,30.3 146.9,30.3 144.73,32.47 144.73,58.89 141.69,61.93 107.1,61.93 104.7,59.52 104.7,12.43
5V0\G on TOP: 99.42,103.67 104.75,103.67 105.13,103.29 105.13,99.35 104.88,99.1 99.42,99.1 99.16,99.35 99.16,103.42
5V0\G on TOP: 32.61,57.57 32.61,54.65 32.36,54.39 28.68,54.39 28.42,54.65 28.42,56.81 27.92,57.31 24.49,57.31 23.98,57.82 23.98,58.97 24.36,59.35 28.42,59.35 29.95,57.82 32.36,57.82
5V0\G on BOTTOM: 107.29,87.54 111.61,87.54 111.99,87.16 111.99,83.86 111.74,83.6 107.16,83.6 106.91,83.86 106.91,87.16
5V0_MOS\G on TOP: 85.7,97.45 85.95,97.19 85.95,93.76 85.7,93.51 83.03,93.51 82.78,93.76 82.78,97.19 83.03,97.45
5V0_MOS\G on TOP: 129.79,104.52 130.05,104.27 130.05,103.12 130.3,102.87 135.13,102.87 135.38,103.12 135.38,105.79 135.13,106.05 130.3,106.05 130.18,105.92 130.18,105.28 129.92,105.03 128.14,105.03 128.02,104.9 128.02,104.65 128.14,104.52
5V0_MOS\G on TOP: 30.61,121.03 30.61,116.08 30.35,115.82 28.7,115.82 28.32,116.2 28.32,121.03 28.45,121.16 30.48,121.16
5V0_MOS\G on TOP: 149.58,30.52 149.33,30.77 149.33,35.22 149.71,35.6 154.79,35.6 155.3,36.11 155.3,40.42 155.04,40.68 153.65,40.68 153.26,41.06 153.26,44.49 153.39,44.61 153.65,44.61 153.77,44.49 153.77,42.84 153.9,42.71 159.11,42.71 159.36,42.46 159.36,33.95 158.09,32.68 152.12,32.68 151.61,32.17 151.61,30.77 151.36,30.52
5V0_MOS\G on BOTTOM: 148.57,33.95 148.57,31.15 148.82,30.9 150.22,30.9 150.47,31.15 150.47,34.33 149.96,34.84 146.63,34.84 146.58,34.78 146.58,34.3 146.63,34.25 148.26,34.25
5V0_MOS\G on BOTTOM: 98.91,113.7 99.16,113.96 99.16,118.66 98.91,118.91 96.62,118.91 96.24,118.53 96.24,113.96 96.5,113.7
5V0_VBUS0\G on TOP: 98.4,103.29 98.4,95.41 98.15,95.16 96.62,95.16 96.37,95.41 96.37,103.29 96.75,103.67 98.02,103.67
5V0_VBUS1\G on BOTTOM: 102.85,89.7 105.77,89.7 106.02,89.45 106.02,84.37 105.64,83.98 103.35,83.98 102.72,84.62 102.72,89.57
12V\G on TOP: 18.14,4.23 18.52,3.85 22.96,3.85 23.34,4.23 23.34,6.64 23.09,6.9 18.52,6.9 18.14,6.51
12V\G on TOP: 150.62,72.14 150.62,70.36 150.5,70.23 149.73,70.23 149.61,70.36 149.61,76.71 149.99,77.09 155.57,77.09 155.96,76.71 155.96,72.9 155.57,72.52 151,72.52
12V\G on TOP: 41.63,95.03 41.89,94.78 41.89,91.22 41.63,90.97 37.57,90.97 37.19,91.35 37.19,94.65 37.57,95.03
12V\G on TOP: 132.06,91.19 136.79,91.19 137.64,90.33 147.03,90.33 147.45,89.92 147.45,83.75 147.3,83.6 135.87,83.6 135.1,84.37 130.53,84.37 129.9,85 129.9,89.19 130.02,89.32 131.42,89.32 131.8,89.7 131.8,90.93
12V\G on BOTTOM: 27.03,6.77 27.03,5.88 26.9,5.75 24.61,5.75 24.36,5.5 24.36,4.1 24.11,3.85 19.28,3.85 19.03,4.1 19.03,6.64 19.28,6.9 26.9,6.9
12V\G on BOTTOM: 13.18,50.2 13.18,48.55 13.56,48.17 16.74,48.17 16.99,47.92 16.99,45.63 16.87,45.5 8.48,45.5 8.23,45.76 8.23,47.92 8.48,48.17 11.66,48.17 12.04,48.55 12.04,50.2 12.17,50.33 13.06,50.33
12V\G on BOTTOM: 42.39,94.53 42.39,91.1 42.27,90.97 37.57,90.97 37.19,91.35 37.19,94.65 37.57,95.03 41.89,95.03
12V\G on L03_P2: 19.11,4.05 17.2,5.96 17.2,42.92 14.92,45.2 10.98,45.2 10.59,45.59 10.59,55.07 11.74,56.21 11.74,64.72 16.94,69.93 16.94,77.3 29.14,77.3 35.36,83.52 35.36,88.98 40.32,93.94 80.79,93.94 83.88,90.86 122.99,90.86 125.24,88.61 132.52,88.61 134.3,90.38 145.81,90.38 148.87,87.33 148.87,78.43 152.45,74.85 152.45,73.62 152.06,73.23 145.13,73.23 138.74,79.62 121.34,79.62 117.21,83.75 116.92,84.02 54.08,84.02 52.86,82.8 52.86,80 43.83,80 37.49,73.65 37.49,64.76 36.47,63.74 29.78,63.74 27.1,66.42 27.1,71.62 26.48,72.25 23.26,72.25 22.63,71.62 22.63,62.69 27.32,58 33.42,58 34.44,56.98 34.44,55.62 29.36,50.54 29.36,35.01 34.32,30.05 34.32,29.07 27.83,29.07 26.95,28.19 26.95,12.65 35.55,4.05
+1V2 on BOTTOM: 112.62,44.61 108.56,44.61 108.31,44.87 108.31,48.42 108.81,48.93 112.62,48.93 112.88,48.68 112.88,44.87
+1V2 on L03_P2: 110.67,43.17 110.67,48.35 114.57,48.35 115.21,47.71 115.21,46.82 115.72,46.32 116.9,46.32 117.4,46.82 117.4,48.21 119.19,50 128.29,50 128.8,49.48 128.8,48.76 128.42,48.37 120.54,48.37 120.04,47.87 120.04,44.44 118.76,43.17
GND on TOP, BOTTOM, L02_P1: 5.42,1.02 1.02,5.42 1.02,100.04 39.68,100.04 40.69,101.05 40.69,106.29 34.73,112.25 29.4,112.25 20.76,120.89 1.02,120.89 1.02,122.88 5.42,127.28 94.48,127.28 94.48,124.24 98.52,124.24 98.52,127.28 150.48,127.28 150.48,105.98 163.58,105.98 167.98,101.58 167.98,5.42 163.58,1.02 144.42,1.02 139.42,6.02 84.08,6.02 79.08,1.02
GND on L03_P2: 5.42,1.02 1.02,5.42 1.02,100.04 13.64,100.04 13.64,90.72 14.39,89.97 15.54,89.97 15.8,89.7 15.8,78.27 16.57,77.51 16.54,77.48 16.54,70.1 11.33,64.89 11.33,56.38 10.19,55.24 10.19,45.42 10.81,44.79 14.75,44.79 16.79,42.75 16.79,5.8 18.94,3.64 35.75,3.64 35.85,3.75 37.77,1.83 76.98,1.83 80.95,5.8 80.95,12.03 105.11,12.03 105.11,59.35 107.27,61.52 141.52,61.52 144.32,58.72 144.32,32.3 146.73,29.9 166.93,29.9 166.93,94.61 161.86,99.68 151.19,99.68 142.68,108.19 104.58,108.19 104.06,108.71 104.06,120.9 102.8,122.16 97.43,122.16 91.46,116.19 53.4,116.19 49.72,119.87 39.64,119.87 38.12,118.35 23.3,118.35 20.76,120.89 1.02,120.89 1.02,122.88 5.42,127.28 94.48,127.28 94.48,124.24 98.52,124.24 98.52,127.28 150.48,127.28 150.48,105.98 163.58,105.98 167.98,101.58 167.98,5.42 163.58,1.02 144.42,1.02 139.42,6.02 84.08,6.02 79.08,1.02 ; 1 cut-out
VCC_3.3V on TOP: 137.39,57.82 137.64,57.57 137.64,56.3 137.48,56.13 132.33,56.13 132.08,56.39 132.08,57.53 132.37,57.82
VCC_3.3V on BOTTOM: 112.88,40.3 112.88,39.28 113.01,39.15 114.53,39.15 114.78,38.9 114.78,37.38 114.53,37.12 110.34,37.12 110.08,37.38 110.08,40.93 110.21,41.06 111.35,41.06 111.48,40.93 111.48,40.55 111.61,40.42 112.75,40.42
VCC_3.3V on L03_P2: 128.96,35.42 128.32,36.06 128.32,39.49 127.6,40.21 121.96,40.21 121.45,39.7 120.82,39.7 120.35,39.23 113.18,39.23 112.55,38.6 112.55,37.08 112.16,36.69 111.06,36.69 110.67,37.08 110.67,42.76 118.93,42.76 120.45,44.28 120.45,47.71 120.71,47.97 128.58,47.97 129.21,48.59 129.21,49.65 128.46,50.41 119.02,50.41 116.99,48.38 116.99,46.98 116.73,46.72 115.88,46.72 115.62,46.98 115.62,47.87 114.74,48.75 110.67,48.75 110.67,49.23 113.94,52.5 131.59,52.5 132.51,53.42 132.51,57.48 133.03,58 134.77,58 135.56,57.21 135.56,36.98 134,35.42
VCC_SCI\G on TOP: 21.46,55.54 20.83,54.9 20.83,34.04 21.55,33.31 24.49,33.31 24.99,33.82 24.99,54.77 24.23,55.54
VCC_SCI\G on BOTTOM: 25.53,41.91 21.34,41.91 21.08,42.16 21.08,44.7 21.34,44.96 25.53,44.96 25.78,44.7 25.78,42.16
USBHUB1_VBUS on TOP: 126.49,103.76 126.24,104.01 126.24,107.82 126.87,108.46 128.91,108.46 129.54,109.09 129.54,117.86 129.03,118.36 126.87,118.36 126.49,117.98 126.49,115.82 126.11,115.44 123.95,115.44 123.7,115.7 123.7,120.78 124.08,121.16 133.86,121.16 134.75,120.27 134.75,107.44 134.24,106.93 130.68,106.93 129.92,106.17 129.92,105.41 129.67,105.16 128.02,105.16 127.89,105.03 127.89,104.39 128.02,104.27 129.67,104.27 129.79,104.14 129.79,103.89 129.67,103.76
USBHUB2_VBUS on TOP: 153.01,44.74 153.01,43.22 152.76,42.96 149.2,42.96 148.57,43.6 148.57,48.55 148.95,48.93 154.03,48.93 154.09,48.87 155.49,48.87 155.8,48.55 155.8,47.03 155.55,46.77 154.53,46.77 154.41,46.65 154.41,43.09 154.28,42.96 154.15,42.96 154.03,43.09 154.03,44.74 153.9,44.87 153.14,44.87
USBHUB3_VBUS on TOP: 148.44,33.69 148.18,33.44 144.63,33.44 144.5,33.57 144.5,37.5 145.77,38.77 145.77,40.42 146.03,40.68 148.06,40.68 148.44,40.3
USBHUB3_VBUS on BOTTOM: 148.06,33.57 145.26,33.57 145.14,33.69 145.14,35.72 145.26,35.85 148.06,35.85 148.18,35.72 148.18,35.09 148.06,34.96 146.53,34.96 146.41,34.84 146.41,34.2 146.53,34.07 148.06,34.07 148.18,33.95 148.18,33.69
USBHUB4_VBUS on TOP: 96.88,114.59 97.38,115.1 98.27,115.1 98.53,115.35 98.53,117.64 98.65,117.77 98.91,117.77 99.04,117.64 99.04,115.86 99.16,115.73 99.8,115.73 99.92,115.86 99.92,117.77 99.99,117.83 99.99,118.46 102.59,121.07 108.56,121.07 109.58,120.05 109.58,115.73 109.2,115.35 107.04,115.35 106.78,115.61 106.78,117.77 106.27,118.27 104.24,118.27 103.23,117.26 103.23,110.15 102.72,109.64 97.38,109.64 96.88,110.15
N1721272 on TOP: 32.36,59.98 32.61,59.73 32.61,58.71 32.36,58.46 30.07,58.46 29.44,59.09 29.44,60.74 29.95,61.25 29.95,63.16 29.57,63.54 29.57,64.81 29.69,64.93 30.96,64.93 32.36,63.54
N2053816 on TOP: 117.32,98.08 124.31,98.08 124.69,97.7 124.69,91.22 124.05,90.59 117.7,90.59 116.94,91.35 116.94,97.7
N2072854 on TOP: 129.13,89.19 129.13,81.06 128.75,80.68 119.1,80.68 117.7,82.08 117.7,85.64 118.59,86.52 127.23,86.52 127.99,87.29 127.99,89.19 128.12,89.32 129.01,89.32
N2116419 on TOP: 99.29,98.46 104.24,98.46 104.5,98.21 104.5,95.54 104.33,95.38 99.29,95.38 98.91,95.76 98.91,98.08
N2491369 on TOP: 149.22,70.36 149.1,70.23 148.34,70.23 148.21,70.36 148.21,72.26 147.92,72.55 142.47,72.55 141.86,73.16 141.86,78.23 142.49,78.87 148.72,78.87 149.22,78.36
N2616362 on TOP: 46.01,73.76 46.01,69.44 45.06,68.49 40.11,68.49 39.09,69.51 39.09,79.54 40.23,80.68 49.63,80.68 49.89,80.43 49.89,75.09 49.38,74.59 46.84,74.59
N2616386 on TOP: 44.68,86.26 44.68,82.71 44.17,82.21 38.46,82.21 38.08,82.59 38.08,89.45 38.42,89.79 41.91,89.79 42.16,89.53 42.16,87.25 42.67,86.74 44.2,86.74
N2616386 on BOTTOM: 42.39,90.08 42.39,89.19 42.27,89.06 40.23,89.06 39.98,88.81 39.98,88.68 39.73,88.43 38.08,88.43 37.95,88.56 37.95,89.95 38.2,90.21 42.27,90.21
N2642373 on TOP: 13.31,62.39 22.33,62.39 22.84,61.89 22.84,57.7 22.39,57.25 20.95,57.25 17.65,53.95 17.65,50.93 17.44,50.71 13.31,50.71 12.93,51.09 12.93,62.01
N2642373 on BOTTOM: 11.79,50.33 11.79,48.68 11.66,48.55 10.9,48.55 10.77,48.68 10.77,52.74 11.15,53.12 16.99,53.12 17.25,52.87 17.25,51.09 16.87,50.71 12.17,50.71
N2653678 on TOP: 24.87,14.13 24.87,7.91 24.49,7.53 18.14,7.53 17.76,7.91 17.76,14.01 18.26,14.52 24.49,14.52
N2653678 on BOTTOM: 27.03,8.29 27.03,7.28 26.9,7.15 21.82,7.15 21.57,7.4 21.57,8.67 21.82,8.93 24.61,8.93 25.12,8.42 26.9,8.42
N2653726 on TOP: 14.71,26.33 29.06,26.33 29.31,26.07 29.31,18.07 28.93,17.69 15.09,17.69 13.95,18.83 13.95,25.56
N2753223 on TOP: 155.57,96.39 143.76,96.39 141.86,98.3 141.86,119.51 142.37,120.02 148.59,120.02 149.1,119.51 149.1,106.81 151.64,104.27 155.32,104.27 155.96,103.63 155.96,96.77
N2764036 on TOP: 150.62,88.77 150.62,82.17 151.57,81.22 164.91,81.22 165.35,81.66 165.35,91.06 164.85,91.57 156.46,91.57 156.21,91.31 156.21,89.92 155.7,89.41 151.26,89.41
N2782469 on TOP: 161.16,92.2 153.92,92.2 153.29,92.84 153.29,95.5 153.8,96.01 156.97,96.01 158.12,97.16 161.16,97.16 161.54,96.77 161.54,92.58
N2978313 on TOP: 161.52,47.15 161.27,46.9 156.82,46.9 156.57,47.15 156.57,50.96 156.95,51.35 161.14,51.35 161.52,50.96
N2982528 on TOP: 157.33,23.02 161.14,23.02 161.52,22.64 161.52,18.33 161.27,18.07 157.46,18.07 157.07,18.45 157.07,22.77
N7088770 on TOP: 57.63,66.46 57.63,75.09 57.25,75.48 55.22,75.48 54.97,75.73 54.97,77.76 54.71,78.02 53.19,78.02 52.93,77.76 52.93,75.73 52.68,75.48 51.66,75.48 51.16,74.97 51.16,66.46 51.79,65.82 57,65.82
N7088770 on BOTTOM: 50.01,65.7 56.87,65.7 57.63,66.46 57.63,73.32 57.25,73.7 51.79,73.7 51.66,73.57 51.66,69.89 49.63,67.86 49.63,66.08
N17782138 on TOP: 48.49,65.32 52.68,65.32 52.93,65.06 52.93,62.39 52.68,62.14 48.62,62.14 48.24,62.52 48.24,65.06
N17782138 on BOTTOM: 48.62,64.81 52.55,64.81 52.93,64.43 52.93,62.39 52.68,62.14 48.62,62.14 48.24,62.52 48.24,64.43

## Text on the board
Ref Des/Silkscreen Top: TT000003175R1A/COMP
L03_P2: www.pcbb.com  The  PCB File share  QQ Group:562010407
PAGE_OUTLINE: 6mil | QLiao | AnNing | 120618
PLACE_BOUND_TOP: V-CUT | 203.0mm
DISPLAY_BOTTOM: FIGURE | SIZE | 8.0 | 10.0 | 19.69 | 23.62 | 31.5 | 36.22 | 39.37 | 43.31 | 47.24 | 51.18 | 55.12 | 59.06 | 62.99 | 125.98 | 137.8 | 236.22 | 82.68x35.43 | 106.3x35.43 | 118.11x39.37 | 125.98x39.37 | 118.11x78.74 | DRILL CHART: TOP to BOTTOM | ALL UNITS ARE IN MILS | TOLERANCE | +0.0/-0.0 | +1.97/-1.97 | PLATED | NON-PLATED | QTY | 727 | 2207 | 1 | 2 | 9 | 16 | 6 | 25 | 3 | 5
